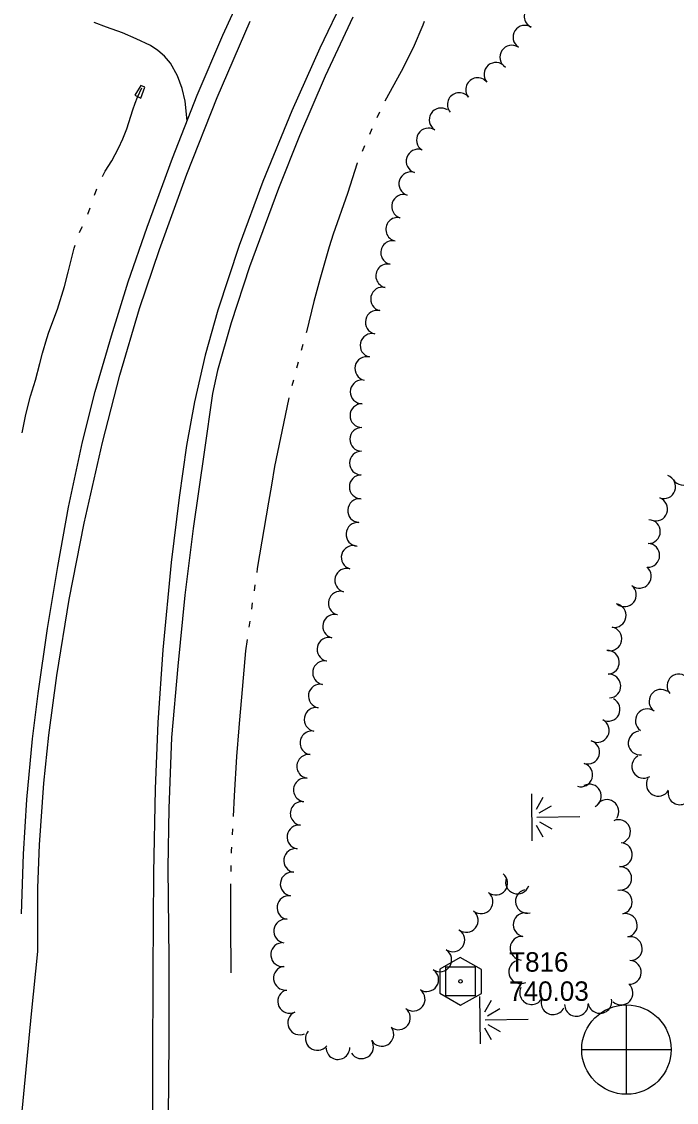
# Model space of a CAD drawing. Extents: x 589250 to 1188077, y 162953 to 363065.
# Drawn here: x 593085.7 to 593287.5, y 165362.3 to 165695.5 of the extents above; entities that cross this region are included whole.
import ezdxf

# ---------------------------------------------------------------- set-up
doc = ezdxf.new("R2010")
doc.units = 0
for name, color, linetype in [('E_DRN', 7, 'Continuous'), ('E_DWY', 7, 'Continuous'), ('E_LAND_TreeLine_P', 7, 'Continuous'), ('E_MAP_Control', 7, 'Continuous'), ('E_MAP_PhotoCenter', 7, 'Continuous'), ('E_RDWY', 7, 'Continuous'), ('E_RDWY_Gravel', 7, 'Continuous'), ('E_WTR_FlowLine', 7, 'Continuous'), ('E_WTR_Wetland', 7, 'Continuous')]:
    doc.layers.add(name, color=color, linetype=linetype)

# ---------------------------------------------------------------- blocks, each defined once
blk = doc.blocks.new('POINT_DISPLAY')
blk.add_line((0, 0), (0, 0))

msp = doc.modelspace()

# ---------------------------------------------------------------- linework, layer by layer
at = {"layer": 'E_DRN'}
for p, q in [((593122.38, 165675.88), (593120.55, 165672.82)), ((593123.61, 165675.31), (593122.38, 165675.88)), ((593122.46, 165671.88), (593123.61, 165675.31)), ((593120.55, 165672.82), (593122.46, 165671.88))]:
    msp.add_line(p, q, dxfattribs=at)
at = {"layer": 'E_DWY'}
for p, q in [((593111.8, 165693.85), (593108.05, 165695.23)), ((593116.73, 165692.02), (593111.8, 165693.85)), ((593120.95, 165690.26), (593116.73, 165692.02)), ((593125.38, 165688.13), (593120.95, 165690.26)), ((593127.62, 165686.59), (593125.38, 165688.13)), ((593129.71, 165684.84), (593127.62, 165686.59)), ((593131.52, 165682.67), (593129.71, 165684.84)), ((593133.7, 165678.82), (593131.52, 165682.67)), ((593135.21, 165674.93), (593133.7, 165678.82)), ((593136.04, 165671.01), (593135.21, 165674.93)), ((593136.67, 165664.91), (593136.04, 165671.01))]:
    msp.add_line(p, q, dxfattribs=at)
at = {"layer": 'E_LAND_TreeLine_P'}
for centre, radius, start, end in [((593244.29, 165697.16), 3.66, 64.1779, 244.1779), ((593240.82, 165690.72), 3.66, 56.7664, 236.7664), ((593236.8, 165684.59), 3.66, 56.7664, 236.7664), ((593231.88, 165679.26), 3.66, 40.2154, 220.2154), ((593226.27, 165674.55), 3.66, 38.9974, 218.9974), ((593220.58, 165669.94), 3.66, 38.9974, 218.9974), ((593214.99, 165665.23), 3.66, 57.6723, 237.6723), ((593211.07, 165659.04), 3.66, 57.6723, 237.6723), ((593207.88, 165652.51), 3.66, 72.308, 252.308), ((593205.65, 165645.53), 3.66, 72.308, 252.308), ((593203.42, 165638.55), 3.66, 72.308, 252.308), ((593201.61, 165631.46), 3.66, 77.7902, 257.7902), ((593200.06, 165624.3), 3.66, 77.7902, 257.7902), ((593198.51, 165617.13), 3.66, 77.7902, 257.7902), ((593196.94, 165609.98), 3.66, 77.2304, 257.2304), ((593195.32, 165602.83), 3.66, 77.2304, 257.2304), ((593193.7, 165595.69), 3.66, 77.2304, 257.2304), ((593192.08, 165588.54), 3.66, 77.2304, 257.2304), ((593190.64, 165581.37), 3.66, 89.441, 269.441), ((593190.57, 165574.04), 3.66, 89.441, 269.441), ((593190.5, 165566.72), 3.66, 89.441, 269.441), ((593190.43, 165559.39), 3.66, 89.441, 269.441), ((593289.61, 165556.29), 3.66, 214.6604, 34.6604), ((593190.36, 165552.06), 3.66, 89.441, 269.441), ((593283.63, 165552.09), 3.66, 250.1869, 70.1869), ((593189.87, 165544.75), 3.66, 85.9125, 265.9125), ((593281.15, 165545.2), 3.66, 250.1869, 70.1869), ((593189.35, 165537.44), 3.66, 85.9125, 265.9125), ((593278.91, 165538.26), 3.66, 268.4056, 88.4056), ((593187.88, 165530.3), 3.66, 74.2386, 254.2386), ((593278.71, 165530.93), 3.66, 268.4056, 88.4056), ((593185.89, 165523.25), 3.66, 74.2386, 254.2386), ((593276.11, 165524.49), 3.66, 231.2705, 51.2705), ((593271.52, 165518.77), 3.66, 231.2705, 51.2705), ((593183.9, 165516.2), 3.66, 74.2386, 254.2386), ((593268.38, 165512.4), 3.66, 259.433, 79.433), ((593182.15, 165509.08), 3.66, 76.2727, 256.2727), ((593267.03, 165505.19), 3.66, 259.433, 79.433), ((593180.41, 165501.96), 3.66, 76.2727, 256.2727), ((593266.28, 165497.95), 3.66, 273.2691, 93.2691), ((593179.07, 165494.76), 3.66, 79.7134, 259.7134), ((593266.7, 165490.64), 3.66, 273.2691, 93.2691), ((593288.32, 165490.68), 3.65, 40.3026, 220.3026), ((593177.76, 165487.55), 3.66, 79.7134, 259.7134), ((593282.76, 165485.93), 3.65, 54.8608, 234.8608), ((593176.45, 165480.34), 3.66, 79.7134, 259.7134), ((593266.49, 165483.45), 3.66, 242.8457, 62.8457), ((593278.55, 165479.96), 3.65, 54.8608, 234.8608), ((593263.14, 165476.93), 3.66, 242.8457, 62.8457), ((593175.17, 165473.13), 3.66, 82.1001, 262.1001), ((593260.2, 165470.25), 3.66, 253.0928, 73.0928), ((593276.33, 165473.05), 3.65, 96.9464, 276.9464), ((593174.16, 165465.87), 3.66, 82.1001, 262.1001), ((593277.46, 165465.87), 3.65, 120.4878, 300.4878), ((593258.07, 165463.24), 3.66, 253.0928, 73.0928), ((593173.15, 165458.61), 3.66, 82.1001, 262.1001), ((593260.73, 165456.7), 3.66, 298.0425, 118.0425), ((593281.92, 165460.34), 3.65, 150.2132, 330.2132), ((593288.61, 165457.69), 3.65, 171.0154, 351.0154), ((593172.15, 165451.35), 3.66, 82.1001, 262.1001), ((593266.11, 165451.96), 3.66, 325.4317, 145.4317), ((593171.14, 165444.1), 3.66, 81.9412, 261.9412), ((593269.7, 165445.76), 3.66, 294.3723, 114.3723), ((593170.11, 165436.84), 3.66, 81.9412, 261.9412), ((593270.27, 165438.64), 3.66, 266.229, 86.229), ((593270.07, 165431.32), 3.66, 270.7429, 90.7429), ((593169.08, 165429.59), 3.66, 81.9412, 261.9412), ((593231.84, 165429.87), 3.66, 231.7235, 51.7235), ((593238.53, 165430.19), 3.66, 160.7598, 340.7598), ((593227.3, 165424.11), 3.66, 231.7235, 51.7235), ((593241.59, 165424.24), 3.66, 104.3134, 284.3134), ((593270.24, 165424), 3.66, 282.2249, 102.2249), ((593168.06, 165422.33), 3.66, 81.9412, 261.9412), ((593222.76, 165418.36), 3.66, 231.7235, 51.7235), ((593240.89, 165417.05), 3.66, 79.702, 259.702), ((593271.79, 165416.84), 3.66, 282.2249, 102.2249), ((593167.03, 165415.08), 3.66, 81.9412, 261.9412), ((593218.6, 165412.34), 3.66, 236.7568, 56.7568), ((593166.14, 165407.82), 3.66, 96.6491, 276.6491), ((593239.94, 165409.8), 3.66, 85.6633, 265.6633), ((593273.34, 165409.68), 3.66, 282.2249, 102.2249), ((593214.58, 165406.21), 3.66, 236.7568, 56.7568), ((593166.98, 165400.54), 3.66, 96.6491, 276.6491), ((593239.52, 165402.52), 3.66, 115.6477, 295.6477), ((593273.02, 165402.36), 3.66, 267.0907, 87.0907), ((593210.56, 165400.08), 3.66, 236.7568, 56.7568), ((593206.39, 165394.07), 3.66, 231.6491, 51.6491), ((593242.88, 165396.1), 3.66, 154.8364, 334.8364), ((593270.47, 165395.96), 3.66, 227.3795, 47.3795), ((593168.31, 165393.4), 3.66, 114.8452, 294.8452), ((593249.51, 165392.98), 3.66, 154.8364, 334.8364), ((593263.96, 165393.38), 3.66, 190.2053, 10.2053), ((593201.84, 165388.32), 3.66, 231.6491, 51.6491), ((593256.71, 165392.48), 3.66, 180.7429, 0.7429), ((593171.39, 165386.75), 3.66, 114.8452, 294.8452), ((593176.85, 165381.97), 3.66, 141.7074, 321.7074), ((593196.72, 165383.22), 3.66, 211.4784, 31.4784), ((593190.47, 165379.39), 3.66, 211.4784, 31.4784), ((593183.19, 165379.16), 3.66, 180.7429, 0.7429)]:
    msp.add_arc(centre, radius, start, end, dxfattribs=at)
at = {"layer": 'E_MAP_Control'}
for p, q in [((593216.46, 165395.06), (593216.46, 165404.06)), ((593216.46, 165404.06), (593225.46, 165404.06)), ((593216.46, 165395.06), (593216.46, 165404.06)), ((593216.46, 165404.06), (593225.46, 165404.06)), ((593225.46, 165404.06), (593225.46, 165395.06)), ((593225.46, 165404.06), (593225.46, 165395.06)), ((593225.46, 165395.06), (593216.46, 165395.06)), ((593225.46, 165395.06), (593216.46, 165395.06))]:
    msp.add_line(p, q, dxfattribs=at)
msp.add_lwpolyline([(593214.55, 165403.32), (593214.55, 165395.93), (593221.01, 165392.21), (593227.4, 165395.87), (593227.4, 165403.2), (593220.88, 165406.92)], close=True, dxfattribs=at)
msp.add_lwpolyline([(593214.55, 165403.32), (593214.55, 165395.93), (593221.01, 165392.21), (593227.4, 165395.87), (593227.4, 165403.2), (593220.88, 165406.92)], close=True, dxfattribs=at)
msp.add_circle((593220.96, 165399.56), 0.546, dxfattribs=at)
msp.add_circle((593220.96, 165399.56), 0.546, dxfattribs=at)
at = {"layer": 'E_MAP_PhotoCenter'}
for p, q in [((593272.08, 165392.34), (593272.02, 165364.93)), ((593272.08, 165392.34), (593272.02, 165364.93)), ((593258.39, 165378.53), (593285.85, 165378.52)), ((593258.39, 165378.53), (593285.85, 165378.52))]:
    msp.add_line(p, q, dxfattribs=at)
msp.add_circle((593272.13, 165378.54), 13.78, dxfattribs=at)
msp.add_circle((593272.13, 165378.54), 13.78, dxfattribs=at)
at = {"layer": 'E_RDWY'}
for p, q in [((593186.08, 165704.96), (593177.59, 165687.32)), ((593145.94, 165672.16), (593156.08, 165695.71)), ((593177.59, 165687.32), (593169, 165668.05)), ((593136.65, 165648.5), (593145.94, 165672.16)), ((593169, 165668.05), (593160.07, 165646.24)), ((593128.18, 165625.24), (593136.65, 165648.5)), ((593160.07, 165646.24), (593152.69, 165626.49)), ((593122, 165607.02), (593128.18, 165625.24)), ((593152.69, 165626.49), (593146.18, 165606.51)), ((593115.93, 165586.55), (593122, 165607.02)), ((593146.18, 165606.51), (593142.25, 165592.64)), ((593142.25, 165592.64), (593138.96, 165578.31)), ((593110.6, 165565.75), (593115.93, 165586.55)), ((593138.96, 165578.31), (593136.54, 165564.77)), ((593104.95, 165540.91), (593110.6, 165565.75)), ((593136.54, 165564.77), (593134.24, 165548.82)), ((593134.24, 165548.82), (593131.76, 165528.75)), ((593100.32, 165517.29), (593104.95, 165540.91)), ((593131.76, 165528.75), (593129.16, 165501.83)), ((593096.49, 165493.91), (593100.32, 165517.29)), ((593129.16, 165501.83), (593127.7, 165479.35)), ((593094.01, 165475.5), (593096.49, 165493.91)), ((593127.7, 165479.35), (593126.86, 165458.9)), ((593092.54, 165460.73), (593094.01, 165475.5)), ((593091.16, 165441.67), (593092.54, 165460.73)), ((593126.86, 165458.9), (593126.29, 165433.05)), ((593090.71, 165428.45), (593091.16, 165441.67)), ((593126.29, 165433.05), (593126.1, 165402.6)), ((593090.62, 165408.73), (593090.71, 165428.45)), ((593088.74, 165389.55), (593090.62, 165408.73)), ((593126.1, 165402.6), (593125.98, 165373.67)), ((593085.67, 165357.39), (593088.74, 165389.55)), ((593125.98, 165373.67), (593125.99, 165356.92))]:
    msp.add_line(p, q, dxfattribs=at)
at = {"layer": 'E_RDWY_Gravel'}
for p, q in [((593147.65, 165691.34), (593154.6, 165706.36)), ((593187.73, 165696.93), (593179.25, 165678.74)), ((593139.78, 165672.84), (593147.65, 165691.34)), ((593179.25, 165678.74), (593171.35, 165660.3)), ((593132.18, 165653.46), (593139.78, 165672.84)), ((593171.35, 165660.3), (593164.88, 165644.03)), ((593124.41, 165632.16), (593132.18, 165653.46)), ((593164.88, 165644.03), (593155.95, 165619.91)), ((593118.51, 165615.25), (593124.41, 165632.16)), ((593155.95, 165619.91), (593150.31, 165602.69)), ((593113.36, 165598.62), (593118.51, 165615.25)), ((593150.31, 165602.69), (593146.01, 165587.93)), ((593108.33, 165581.44), (593113.36, 165598.62)), ((593146.01, 165587.93), (593144.53, 165580.8)), ((593104.48, 165565.96), (593108.33, 165581.44)), ((593144.53, 165580.8), (593141.91, 165562.74)), ((593100.13, 165545.78), (593104.48, 165565.96)), ((593141.91, 165562.74), (593138.54, 165539.19)), ((593096.87, 165527.54), (593100.13, 165545.78)), ((593138.54, 165539.19), (593136, 165518.66)), ((593093.64, 165508.34), (593096.87, 165527.54)), ((593136, 165518.66), (593133.87, 165496.76)), ((593090.81, 165488.35), (593093.64, 165508.34)), ((593133.87, 165496.76), (593131.91, 165474.8)), ((593089.04, 165474.36), (593090.81, 165488.35)), ((593087.3, 165455.64), (593089.04, 165474.36)), ((593131.91, 165474.8), (593131.02, 165452.83)), ((593086.29, 165438.75), (593087.3, 165455.64)), ((593131.02, 165452.83), (593130.74, 165434.54)), ((593085.66, 165420.39), (593086.29, 165438.75)), ((593130.74, 165434.54), (593131.04, 165406.52)), ((593131.04, 165406.52), (593131.02, 165381.44)), ((593131.02, 165381.44), (593130.82, 165357.52))]:
    msp.add_line(p, q, dxfattribs=at)
at = {"layer": 'E_WTR_FlowLine'}
for p, q in [((593209.37, 165694.39), (593206.4, 165687.41)), ((593209.78, 165695.53), (593209.37, 165694.39)), ((593206.4, 165687.41), (593202.7, 165680.13)), ((593202.7, 165680.13), (593197.67, 165670.98)), ((593121.41, 165672.25), (593122.74, 165675.16)), ((593119.92, 165668.32), (593120.65, 165670.43)), ((593120.65, 165670.43), (593121.41, 165672.25)), ((593118.1, 165662.47), (593119.92, 165668.32)), ((593196, 165667.59), (593195.17, 165665.9)), ((593116.85, 165659.36), (593118.1, 165662.47)), ((593193.6, 165662.46), (593192.87, 165660.72)), ((593115.55, 165656.46), (593116.85, 165659.36)), ((593191.39, 165657.24), (593190.65, 165655.5)), ((593113.5, 165652.64), (593115.55, 165656.46)), ((593111.47, 165649.38), (593113.5, 165652.64)), ((593189.1, 165651.84), (593186.1, 165642.52)), ((593189.18, 165652.02), (593189.1, 165651.84)), ((593110.61, 165647.74), (593111.47, 165649.38)), ((593108.13, 165642.05), (593108.88, 165643.98)), ((593186.1, 165642.52), (593181.68, 165629.95)), ((593106.11, 165636.16), (593106.78, 165638.12)), ((593103.51, 165630.51), (593103.6, 165630.78)), ((593103.6, 165630.78), (593104.39, 165632.39)), ((593181.68, 165629.95), (593180.52, 165626.03)), ((593100.06, 165618.26), (593101.92, 165625.66)), ((593101.92, 165625.66), (593102.22, 165626.57)), ((593180.52, 165626.03), (593177.58, 165616.05)), ((593098.89, 165613.84), (593100.06, 165618.26)), ((593096.74, 165606.9), (593098.89, 165613.84)), ((593177.58, 165616.05), (593175.71, 165609.17)), ((593094.06, 165599.78), (593096.74, 165606.9)), ((593175.71, 165609.17), (593173.47, 165599.84)), ((593092.07, 165593.33), (593093.46, 165597.82)), ((593093.46, 165597.82), (593094.06, 165599.78)), ((593173.47, 165599.84), (593173.4, 165599.58)), ((593172.4, 165595.93), (593171.9, 165594.11)), ((593091.24, 165590.09), (593092.07, 165593.33)), ((593170.9, 165590.47), (593170.6, 165589.39)), ((593089.91, 165584.94), (593091.24, 165590.09)), ((593170.6, 165589.39), (593170.4, 165588.64)), ((593088.43, 165579.99), (593089.91, 165584.94)), ((593169.44, 165584.99), (593168.95, 165583.17)), ((593086.98, 165574.34), (593088.43, 165579.99)), ((593168.05, 165579.5), (593166.37, 165571.63)), ((593085.84, 165568.73), (593086.98, 165574.34)), ((593166.37, 165571.63), (593163.63, 165558.33)), ((593163.63, 165558.33), (593162.69, 165552.63)), ((593162.69, 165552.63), (593161.82, 165547.31)), ((593161.82, 165547.31), (593158.32, 165526.85)), ((593158.32, 165526.85), (593158.14, 165525.61)), ((593157.58, 165521.87), (593157.31, 165520)), ((593156.76, 165516.26), (593156.5, 165514.39)), ((593155.99, 165510.65), (593155.74, 165508.78)), ((593155.23, 165505.03), (593154.74, 165501.46)), ((593154.74, 165501.46), (593153.41, 165487.21)), ((593153.41, 165487.21), (593152.73, 165479.12)), ((593152.62, 165477.76), (593151.95, 165468.88)), ((593152.73, 165479.12), (593152.62, 165477.76)), ((593151.95, 165468.88), (593151.18, 165456.79)), ((593151.18, 165456.79), (593150.86, 165450.41)), ((593150.67, 165446.64), (593150.57, 165444.75)), ((593150.38, 165440.98), (593150.32, 165439.78)), ((593150.32, 165439.78), (593150.3, 165439.09)), ((593150.2, 165435.31), (593150.15, 165433.42)), ((593150.05, 165429.64), (593150.02, 165428.78)), ((593150.02, 165428.78), (593150.03, 165417.52)), ((593150.03, 165417.52), (593150.19, 165402.24))]:
    msp.add_line(p, q, dxfattribs=at)
at = {"layer": 'E_WTR_Wetland'}
for p, q in [((593242.81, 165457.43), (593243, 165442.87)), ((593246.34, 165456.22), (593244.33, 165452.57)), ((593245.27, 165451.5), (593249.03, 165453.72)), ((593257.73, 165450.31), (593244.53, 165450.14)), ((593246.5, 165444.05), (593244.4, 165447.65)), ((593245.3, 165448.74), (593249.12, 165446.63)), ((593226.87, 165394.91), (593227.05, 165380.35)), ((593230.4, 165393.71), (593228.39, 165390.06)), ((593229.32, 165388.99), (593233.08, 165391.2)), ((593241.79, 165387.8), (593228.58, 165387.62)), ((593230.56, 165381.53), (593228.46, 165385.13)), ((593229.36, 165386.23), (593233.18, 165384.11))]:
    msp.add_line(p, q, dxfattribs=at)

# ---------------------------------------------------------------- block references
at = {"layer": 'E_WTR_Wetland', "rotation": 89.2570511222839}
for p in [(593242.9, 165450.59), (593242.9, 165450.1), (593242.9, 165450.04), (593244.53, 165450.14), (593245.79, 165450.16), (593226.95, 165388.07), (593226.96, 165387.58), (593226.96, 165387.52), (593228.58, 165387.62), (593229.84, 165387.64)]:
    msp.add_blockref('POINT_DISPLAY', p, dxfattribs=at)

# ---------------------------------------------------------------- texts
at = {"layer": 'E_MAP_Control'}
for s, p in [('T816', (593235.97, 165402.56)), ('T816', (593235.97, 165402.56)), ('740.03', (593235.97, 165393.56)), ('740.03', (593235.97, 165393.56))]:
    msp.add_text(s, height=6, dxfattribs=at).set_placement(p)

doc.saveas('drawing.dxf')
